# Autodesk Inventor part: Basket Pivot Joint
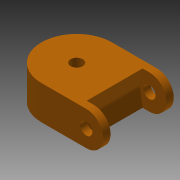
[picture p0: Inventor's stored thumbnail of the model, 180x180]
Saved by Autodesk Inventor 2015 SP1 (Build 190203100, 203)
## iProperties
Created: 2008-11
Part Number: Basket Pivot Joint
Document SubType Name: Modeling
Designer: dwoollam
Density: 7.85 g/cm^3
Material: Steel
Appearance: Orange
Mass: 86938.5 g
Surface Area: 3814.1 cm^2
Volume: 11075 cm^3
Dwg_Category: Clearance_Mewp
INSTALLATION: False
CIVIL_WORK: False
EARTHING: False
MOUNTING: False
Author: dwoollam
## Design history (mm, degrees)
sketch "Sketch1"
  geometry: L1 (0, 145)-(100, 145); L2 (0, -145)-(100, -145); L3 (100, -145)-(100, 145); C1 r 25 at (0, 0); A1 r 145 centre (0, 0) between (0, 145) and (0, -145); 1 further point
  constraints: 6 end point, 2 centre point, 2 coincident, 2 point on circle, 2 tangent, 1 horizontal, 1 parallel, 1 vertical
  dimensions: "d0" = 50 diameter of C1; "d1" = 290 diameter of A1; "d2" = 100 distance from line of point (0, 0) L3
extrude "Body_P1" new body sketch "Sketch1" stored distance "d3" = 140; taper "d4" = 0 deg
sketch "Sketch2"
  geometry: L1 (25, -70)-(-25, -70) reference; L2 (-25, 70)-(25, 70) reference; L3 (-100, -70)-(-100, 70) reference; L4 (-100, 70)-(-184.5, 70); L5 (-100, -70)-(-184.5, -70); L6 (-145.108, 6.946)-(-156.226, 70); L7 (-145.108, -6.946)-(-156.226, -70); L8 (-100, -70)-(-100, 70); C1 r 25 at (-184.5, 0); A1 r 40 centre (-184.5, 0) between (-145.108, -6.946) and (-145.108, 6.946); A2 r 70 centre (-184.5, 0) between (-184.5, 70) and (-184.5, -70); 2 further points
  constraints: 10 end point, 4 point on circle, 3 centre point, 3 tangent, 2 coincident, 2 perpendicular, 2 point on line, 1 horizontal alignment, 1 midpoint, 1 parallel, 1 vertical alignment
  dimensions: "d5" = 84.5 distance from line of L3 C1.centre; "d6" = 80 diameter of A1; "d7" = 50 diameter of C1; "d8" = 80 deg angle of L5 L7
  node "Projected Loop1"
extrude "Body_P2" join sketch "Sketch2" stored distance "d9" = 290; taper "d10" = 0 deg
extrude "Body_P2_Sub" cut sketch "Sketch2" stored distance "d11" = 230; taper "d12" = 0 deg
body "Solid1"
